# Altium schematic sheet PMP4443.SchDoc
size 431 x 279 mm; Date: Not shown in title block; ApprovedBy: Not shown in title block; CheckedBy: Not shown in title block; Author: Not shown in title block; CompanyName: Not shown in title block; Engineer: Not shown in title block; Organization: Not shown in title block; Address1: Not shown in title block; Address2: Not shown in title block; Address3: Not shown in title block; Address4: Not shown in title block; DocumentNumber: 1; Revision: Use project parameter SCH_Rev; SheetNumber: 1; SheetTotal: 1; PageSetup: Record=PageOptions|CenterHorizontal=True|CenterVertical=True|PrintScale=1.00|XCorrection=1.00|YCorrection=1.00|PrintKind=0|BorderSize=5000000|LeftOffset=0|BottomOffset=0|Orientation=2|PaperLength=1000|PaperWidth=1000|Scale=100|PaperSource=15|PrintQuality=600|MediaType=1|DitherType=10|PaperKind=Letter|PrintScaleMode=1
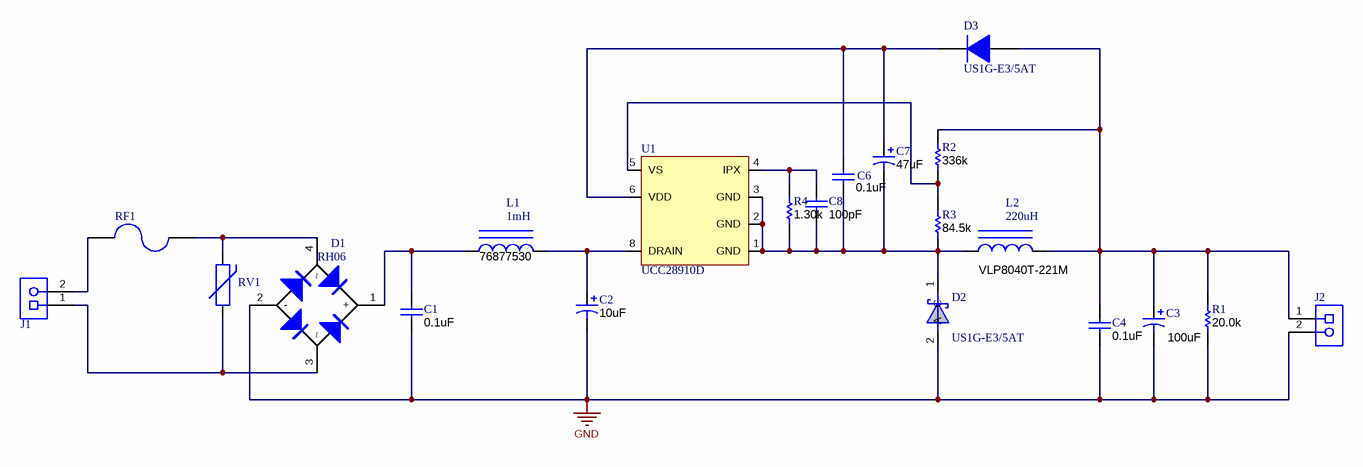
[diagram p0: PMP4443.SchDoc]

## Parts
C1  ValueDisplayed: 0.1uF  [1812]  (hidden comment: VJ1812Y104KXEAT5Z)
C2  ValueDisplayed: 10uF  [VR_1000x1250]  (hidden comment: UVC2G100MPD)
C3  ValueDisplayed: 100uF  [CAPSMT_62_HA0]  (hidden comment: EMVA500ADA101MHA0G)
C4  ValueDisplayed: 0.1uF  [1206]  (hidden comment: 12065C104JAT2A)
C6  ValueDisplayed: 0.1uF  [0603]  (hidden comment: 06033D104KAT2A)
C7  ValueDisplayed: 47uF  [FM_500x1100]  (hidden comment: EEU-FM1E470)
C8  ValueDisplayed: 100pF  [0603]  (hidden comment: 06033C101KAT2A)
D1  RH06  [MiniDIP]
D2  US1G-E3/5AT  [DO-214AC]
D3  US1G-E3/5AT  [SMA]
J1  20020110-H021A01LF  [FCI_20020110-H021A01LF]  (value not drawn)
J2  20020110-H021A01LF  [FCI_20020110-H021A01LF]  (value not drawn)
L1  1mH  [WE-PD2-L]
L2  220uH  PartNumber: VLP8040T-221M  [VLP8040T]
R1  value 20.0k  [1206]  (hidden comment: RC1206FR-0720KL)
R2  value 336k  [0603]  (hidden comment: RT0603DRE07336KL)
R3  value 84.5k  [0603]  (hidden comment: RT0603DRE0784K5L)
R4  value 1.30k  [0603]  (hidden comment: CRCW06031K30FKEA)
RF1  PWR4522AS8R20JA  [RES_PWR4522]  (value not drawn)
RV1  S10K275E2  [VAR_S10K275E2]  (value not drawn)
U1  UCC28910D  [D0007A_N]

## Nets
GND: C1.2 C2.2(-) C3.2(-) C4.2 D1.2(-) D2.2(A) J2.2 R1.1
NetC1_1: C1.1 D1.1(+) L1.1
NetC2_1: C2.1(+) L1.2 U1.8(DRAIN)
NetC3_1: C3.1(+) C4.1 D3.2(A) J2.1 L2.2 R1.2 R2.2
NetC6_1: C6.1 C7.1(+) D3.1(K) U1.6(VDD)
NetC6_2: C6.2 C7.2(-) C8.2 D2.1(C) L2.1 R3.1 R4.1 U1.1(GND) U1.2(GND) U1.3(GND)
NetC8_1: C8.1 R4.2 U1.4(IPX)
NetD1_3: D1.3 J1.1 RV1.1
NetD1_4: D1.4 RF1.1 RV1.2
NetJ1_2: J1.2 RF1.2
NetR2_1: R2.1 R3.2 U1.5(VS)

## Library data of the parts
C1 = VJ1812Y104KXEAT5Z: CAP, CERM, 0.1uF, 500V, +/-10%, X7R, 1812; Manufacturer: Vishay-Vitramon; Polarized: N; CompType: Capacitor; U/M: EA; Cap_F: 0.0000001; Tolerance_%: 10; Value1: Unknown; VDC_V: 500; TaMin_C: -55; TaMax_C: 125
C2 = UVC2G8R2MPD: CAP, AL, 10uF, 400V, +/-20%, TH; Manufacturer: Nichicon; Polarized: Y; CompType: Capacitor; U/M: EA; Cap_F: 0.0000082; Tolerance_%: 20; Value1: Unknown; VDC_V: 400; IRMS_A: 0.085; TaMin_C: -40; TaMax_C: 105; Cap_Case: 10*mm
C3 = EMVA500ADA101MHA0G: CAP, AL, 100uF, 50V, +/-20%,  ohm, SMD; Manufacturer: Nippon Chemi-Con; Polarized: Y; CompType: Capacitor; U/M: EA; Cap_F: 0.0001; Tolerance_%: 20; Value1: Unknown; VDC_V: 50; IRMS_A: 0.19; TaMin_C: -40; TaMax_C: 85; Cap_Case: HA0
C4 = 12065C104JAT2A: CAP, CERM, 0.1uF, 50V, +/-5%, X7R, 1206; Manufacturer: AVX; Polarized: N; CompType: Capacitor; U/M: EA; Cap_F: 0.0000001; Tolerance_%: 5; ESR_Ohm: 0.037; Value1: 0.037 ohm; VDC_V: 50; TaMin_C: -55; TaMax_C: 125
C6 = 06033D104KAT2A: CAP, CERM, 0.1uF, 25V, +/-10%, X5R, 0603; Manufacturer: AVX; Polarized: N; CompType: Capacitor; U/M: EA; Cap_F: 0.0000001; Tolerance_%: 10; ESR_Ohm: 0.048; Value1: 0.048 ohm; VDC_V: 25; IRMS_A: 0.53; TaMin_C: -55; TaMax_C: 85
C7 = EEU-FM1E470: CAP, AL, 47uF, 25V, +/-20%, 0.3 ohm, TH; Manufacturer: Panasonic; Polarized: Y; CompType: Capacitor; U/M: EA; Cap_F: 0.000047; Tolerance_%: 20; Value1: 0.3 ohm; VDC_V: 25; ESR_Ohm: 0.3; IRMS_A: 0.28; TaMin_C: -40; TaMax_C: 105; Cap_Case: 5x11
C8 = 06033C101KAT2A: CAP, CERM, 100pF, 25V, +/-10%, X7R, 0603; Manufacturer: AVX; Polarized: N; CompType: Capacitor; U/M: EA; Cap_F: 0.0000000001; Tolerance_%: 10; Value1: Unknown; VDC_V: 25; TaMin_C: -55; TaMax_C: 125
D1 = RH06-T: Diode, Switching-Bridge, 600V, 0.5A, MiniDIP; Manufacturer: Diodes Inc.; U/M: EA; Vf_V: 1.15; Value2: 1.15V; Io_A: 0.5; Vr_V: 600; TJmax_C: 150
D2 = D_SCHOT_SS_SERIES: Diode, Schottky, xxV, 1A; PartNumber: SS1x; Manufacturer: Vishay; Area: 37520; Value: SS1x
D3 = MURA160T3G: Diode, Ultrafast, 600V, 1A, SMA; Manufacturer: ON Semiconductor; U/M: EA; Vf_V: 1.05; Value2: 1.05V; Io_A: 1; Vr_V: 600; TJmax_C: 175
J1 J2 = 20020110-H021A01LF: Terminal Block, 2x1, 5.08mm, TH; Manufacturer: FCI; SymbolCreator: a0412235; U/M: EA
L1 = 76877530: Inductor, Unshielded Drum Core, Metal Composite, 1mH, 0.3A, 2.78 ohm, SMD; Manufacturer: Wurth Elektronik eiSos; Ind_H: 1.0E-3; Imax_A: 0.3; Irms: 0.3A @ 40C rise; Isat: 0.3A @ 10% inductance drop; DCR_ohm: 2.78
L2 = 744775247: Inductor, Metal Composite, 2200uH, 0.6A, 0.61ohm, SMD; Manufacturer: TDK; Value: 470uH; Ind_H: 470.0E-6; ValueDisplayed: 470µH; Imax_A: 0.36; Irms: 0.36A @ 40C rise; Isat: 0.38A @ 10% inductance drop; DCR_ohm: 1.37; Value1: 1.37 ohm; Value2: 0.36A
R1 = RC1206FR-0720KL: RES, 20.0k ohm, 1%, 0.25W, 1206; Manufacturer: Yageo America; CompType: Resistor; Res_ohm: 20000; Value_Code: 20k0; Tolerance_%: 1; Power_W: 0.25; VDC_V: 200; TempCo: 100 ppm/C; EIA_Code: E96; U/M: EA
R2 = RT0603DRE07336KL: RES, 336k ohm, 0.5%, 0.1W, 0603; Manufacturer: Yageo America; CompType: Resistor; Res_ohm: 336000; Tolerance_%: 0.5; Power_W: 0.1; VDC_V: 75; TempCo: 50 ppm/C; EIA_Code: E192; U/M: EA
R3 = RT0603DRE0784K5L: RES, 84.5k ohm, 0.5%, 0.1W, 0603; Manufacturer: Yageo America; CompType: Resistor; Res_ohm: 84500; Value_Code: 84k5; Tolerance_%: 0.5; Power_W: 0.1; VDC_V: 75; TempCo: 50 ppm/C; EIA_Code: E192; U/M: EA
R4 = CRCW06031K30FKEA: RES, 1.30k ohm, 1%, 0.1W, 0603; Manufacturer: Vishay-Dale; CompType: Resistor; Res_ohm: 1300; Value_Code: 1k30; Tolerance_%: 1; Power_W: 0.1; VDC_V: 75; TempCo: 100 ppm/C; EIA_Code: E96; U/M: EA
RF1 = PWR4522AS8R20JA: RES, 8.2 ohm, 5%, 3W, Fusible, TH; Manufacturer: Bourns; SymbolCreator: a0412235; CompType: Fusible Resistor; Res_ohm: 8.2; Value: 8.2; Value_Code: 8R20; Tolerance_%: 5; Power_W: 3; TempCo: 90 ppm/C; EIA_Code: E24; U/M: EA
RV1 = S10K275E2: Varistor 275V RMS 10MM Radial, TH; Manufacturer: EPCOS Inc; SymbolCreator: a0412235
U1 = UCC28910D: LOW STAND-BY POWER, CV / CC PWM HV SWITCHER WITH PRIMARY SIDE REGULATION, D0007A; Alternate Manufacturer: None; Manufacturer: Texas Instruments; SymbolCreator: a0412235; CompType: IC; U/M: EA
